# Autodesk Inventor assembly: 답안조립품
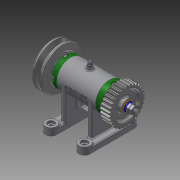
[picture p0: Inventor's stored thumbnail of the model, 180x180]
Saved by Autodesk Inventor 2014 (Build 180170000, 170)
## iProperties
Created: 2015-11
Part Number: 답안조립품
Document SubType Name: Assembly
Designer: test_24
Author: test_24
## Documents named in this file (13)
- C:\Users\test_24\Desktop\20151128\답안조립품.iam
- C:\Users\test_24\Desktop\20151128\1-본체.ipt
- C:\Users\test_24\Desktop\20151128\451109V1038\축.ipt
- C:\Users\test_24\Desktop\20151128\451109V1038\베어링 15 x 32 x 9.ipt
- C:\Users\test_24\Desktop\20151128\451109V1038\커버.ipt
- C:\Users\test_24\Desktop\20151128\451109V1038\키 3 x 3 x 12.ipt
- C:\Users\test_24\Desktop\20151128\451109V1038\스퍼기어.ipt
- C:\Users\test_24\Desktop\20151128\451109V1038\V벨트풀리.ipt
- C:\Users\test_24\Desktop\20151128\451109V1038\와셔 8x17.ipt
- C:\Users\test_24\Desktop\20151128\451109V1038\스프링와셔 8.ipt
- C:\Users\test_24\Desktop\20151128\451109V1038\너트 M 8.ipt
- C:\Users\test_24\Desktop\20151128\451109V1038\볼트 M4 x 12.ipt
- C:\Users\test_24\Desktop\20151128\451109V1038\니플 M 6 x 0.75.ipt
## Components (12 placed, 4 different names)
1. 1-본체:1
2. KS B 2023 6002 - 15 x 32 x 9:1
3. KS B 2023 6002 - 15 x 32 x 9:2
4. V벨트풀리:1
5. ISO 4762 M4 x 12:3
6. ISO 4762 M4 x 12:4
7. ISO 4762 M4 x 12:5
8. ISO 4762 M4 x 12:6
9. ISO 4762 M4 x 12:2
10. ISO 4762 M4 x 12:7
11. ISO 4762 M4 x 12:8
12. ISO 4762 M4 x 12:9
